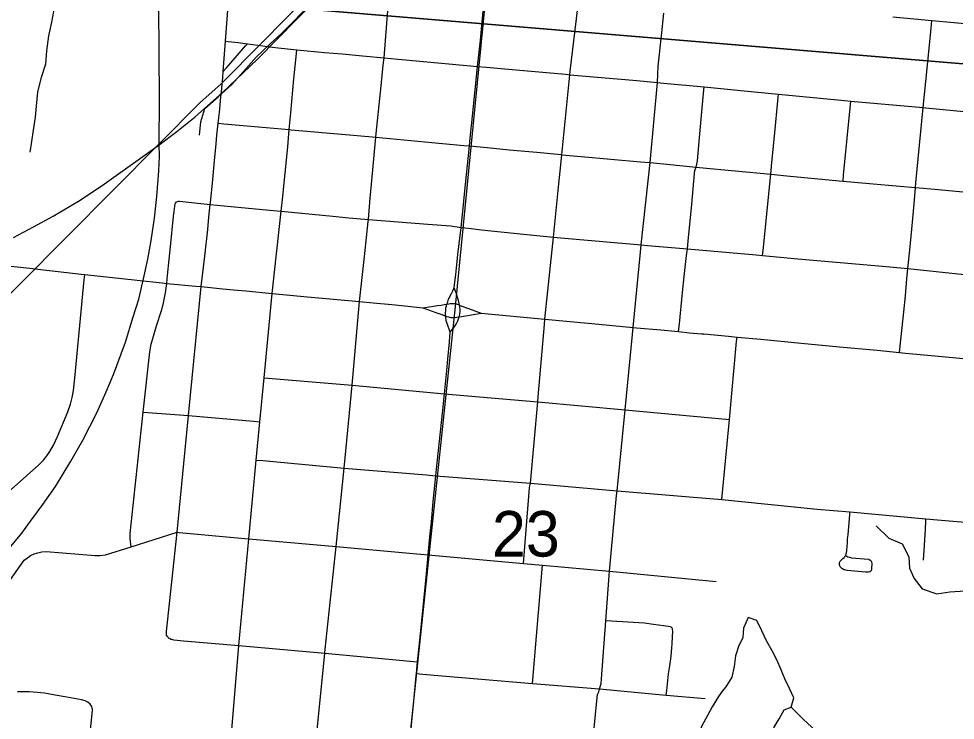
# Model space of a CAD drawing. Extents: x 0 to 1067, y 0 to 440.
# Drawn here: x 801.667 to 802.528, y 351.834 to 352.478 of the extents above; entities that cross this region are included whole.
import ezdxf

# ---------------------------------------------------------------- set-up
doc = ezdxf.new("R2010")
doc.units = 0
for name, color, linetype in [('GM_X_City_Street', 7, 'Continuous'), ('GM_X_Minor_Lake', 7, 'Continuous'), ('GM_X_Minor_River', 7, 'Continuous'), ('GM_X_Rail_Line', 7, 'Continuous'), ('GM_X_Section', 7, 'Continuous'), ('GM_X_Section_Text', 7, 'Continuous'), ('GM_X_State_Route', 7, 'Continuous'), ('GM_X_US_Route', 7, 'Continuous')]:
    doc.layers.add(name, color=color, linetype=linetype)

msp = doc.modelspace()

# ---------------------------------------------------------------- linework, layer by layer
at = {"layer": 'GM_X_City_Street'}
for p, q in [((801.90043, 352.22587), (801.90867, 352.30157)), ((801.89306, 352.14836), (801.90043, 352.22587)), ((801.89306, 352.14836), (801.9737, 352.14146)), ((801.9737, 352.14146), (802.05865, 352.1337)), ((802.05865, 352.1337), (802.14441, 352.12612)), ((802.14441, 352.12612), (802.22463, 352.11878)), ((802.22463, 352.11878), (802.32063, 352.10989)), ((802.05076, 352.05842), (802.13765, 352.05156)), ((802.13765, 352.05156), (802.21744, 352.04445)), ((802.21744, 352.04445), (802.31357, 352.03647)), ((802.43117, 352.02507), (802.501, 352.01891)), ((801.77068, 351.993), (801.81286, 352.00644)), ((801.87888, 352.00035), (801.95916, 351.99336)), ((802.1395, 351.8674), (802.14869, 351.97616))]:
    msp.add_line(p, q, dxfattribs=at)
for points in [[(802.17382, 352.42684), (802.1742, 352.43015), (802.18315, 352.50645), (802.18406, 352.5112), (802.18522, 352.51941), (802.1918, 352.58708), (802.19873, 352.6575), (802.20495, 352.72824), (802.20556, 352.73524)], [(802.00311, 352.44223), (802.00451, 352.45834), (802.00696, 352.48961), (802.00897, 352.51285)], [(801.83503, 352.23223), (801.8385, 352.26019), (801.84106, 352.28473), (801.84222, 352.29577), (801.84343, 352.30764), (801.84361, 352.30935), (801.84542, 352.32729), (801.84732, 352.34771), (801.84882, 352.36315), (801.8496, 352.37119), (801.85078, 352.38219), (801.85187, 352.39218), (801.85325, 352.4064), (801.85368, 352.41101), (801.85494, 352.42436), (801.85536, 352.42984), (801.85751, 352.45776), (801.85999, 352.49)], [(802.23932, 352.27038), (802.24764, 352.34603), (802.25435, 352.41974), (802.25471, 352.42722), (802.25507, 352.43471), (802.25825, 352.46537), (802.26019, 352.48345)], [(802.47071, 352.47984), (802.49032, 352.47813), (802.50649, 352.47663)], [(802.47665, 352.17162), (802.47728, 352.17745), (802.48064, 352.2089), (802.48218, 352.22371), (802.48352, 352.23916), (802.48441, 352.24872), (802.48621, 352.2657), (802.48807, 352.28484), (802.48904, 352.29466), (802.49005, 352.3082), (802.49144, 352.32326), (802.49181, 352.32737), (802.49853, 352.39661), (802.50104, 352.42052), (802.50578, 352.46932), (802.50649, 352.47663)], [(802.50649, 352.47663), (802.52697, 352.47474), (802.57406, 352.47004), (802.6483, 352.46263), (802.69617, 352.45813), (802.70031, 352.45774)], [(801.85536, 352.42984), (801.85822, 352.4331), (801.86623, 352.4422), (801.87593, 352.45325), (801.87768, 352.45524)], [(801.85751, 352.45776), (801.85999, 352.45747), (801.8691, 352.45641), (801.87768, 352.45524), (801.8824, 352.45463), (801.89157, 352.45337), (801.89535, 352.45286), (801.90581, 352.4516), (801.92292, 352.4497), (801.94829, 352.44728), (801.96495, 352.44588), (801.98338, 352.44412), (802.00311, 352.44223), (802.01593, 352.441), (802.07922, 352.43532), (802.08908, 352.43434)], [(801.90867, 352.30157), (801.90971, 352.31203), (801.91469, 352.36065), (801.916, 352.37632), (801.9173, 352.39191), (801.92027, 352.42315), (801.92257, 352.44614), (801.92292, 352.4497)], [(801.98061, 352.21846), (801.98556, 352.26268), (801.98857, 352.29186), (801.98877, 352.29393), (801.98954, 352.30169), (801.99046, 352.3134), (801.99156, 352.32638), (801.99564, 352.36936), (801.99596, 352.37264), (802.00035, 352.41645), (802.00237, 352.43565), (802.00311, 352.44223)], [(802.08908, 352.43434), (802.09722, 352.4336), (802.11755, 352.43179), (802.1698, 352.42718), (802.17382, 352.42684), (802.2353, 352.42145), (802.25435, 352.41974), (802.25995, 352.41905), (802.29708, 352.41559), (802.33092, 352.41244), (802.36552, 352.40905), (802.42622, 352.40311), (802.43205, 352.40258), (802.49853, 352.39661), (802.50094, 352.3964), (802.66594, 352.38059), (802.69396, 352.37809), (802.73883, 352.37338), (802.75724, 352.37145), (802.81158, 352.36564), (802.86823, 352.36027), (802.87525, 352.35961)], [(802.15083, 352.20225), (802.15869, 352.27757), (802.1638, 352.32651), (802.16488, 352.33818), (802.16641, 352.35331), (802.17382, 352.42684)], [(802.27376, 352.19076), (802.27448, 352.19797), (802.27735, 352.22675), (802.27885, 352.24148), (802.27939, 352.24694), (802.28103, 352.26071), (802.28183, 352.26671), (802.28267, 352.27394), (802.28594, 352.30777), (802.2882, 352.336), (802.2888, 352.33886), (802.28976, 352.342), (802.29058, 352.34459), (802.29099, 352.34759), (802.29336, 352.37248), (802.29685, 352.41292), (802.29708, 352.41559)], [(802.35089, 352.26074), (802.35135, 352.26531), (802.35835, 352.33534), (802.35936, 352.34626), (802.36181, 352.37038), (802.36522, 352.40589), (802.36552, 352.40905)], [(802.42481, 352.32905), (802.42536, 352.33464), (802.43205, 352.40258)], [(801.85078, 352.38219), (801.85599, 352.38175), (801.89481, 352.37844), (801.916, 352.37632), (801.91766, 352.37616), (801.97832, 352.37097), (801.99564, 352.36936), (802.04691, 352.36459), (802.07646, 352.3619), (802.08159, 352.36142)], [(802.08159, 352.36142), (802.09775, 352.3598), (802.1181, 352.35775), (802.14333, 352.3555), (802.16555, 352.35339), (802.16641, 352.35331), (802.18409, 352.35173), (802.23887, 352.34686), (802.24764, 352.34603), (802.2629, 352.34457), (802.28976, 352.342), (802.29299, 352.34156), (802.35835, 352.33534), (802.37325, 352.33392), (802.42128, 352.32937), (802.42481, 352.32905), (802.44912, 352.32686), (802.47707, 352.32447), (802.49144, 352.32326), (802.5125, 352.32139), (802.57344, 352.31554)], [(801.80347, 352.23506), (801.8042, 352.24238), (801.80565, 352.2571), (801.80683, 352.26857), (801.80973, 352.29679), (801.81022, 352.301), (801.81088, 352.30603), (801.81125, 352.30804), (801.81156, 352.30887), (801.812, 352.30956), (801.81255, 352.31005)], [(801.81255, 352.31005), (801.81335, 352.31042), (801.81428, 352.31054), (801.81521, 352.31048), (801.8234, 352.30962), (801.84343, 352.30764)], [(801.84343, 352.30764), (801.84974, 352.30702), (801.89779, 352.30247), (801.90867, 352.30157)], [(801.90867, 352.30157), (801.95603, 352.29688), (801.97088, 352.29543), (801.98877, 352.29393)], [(801.98877, 352.29393), (802.04321, 352.28962), (802.06444, 352.28783), (802.07384, 352.28652)], [(802.07384, 352.28652), (802.08069, 352.28578), (802.09254, 352.28426), (802.13131, 352.28031), (802.15869, 352.27757)], [(802.15869, 352.27757), (802.16565, 352.27687), (802.23932, 352.27038)], [(802.23196, 352.19455), (802.23881, 352.26381), (802.23932, 352.27038)], [(802.23932, 352.27038), (802.24519, 352.26986), (802.28183, 352.26671)], [(802.28183, 352.26671), (802.34489, 352.26129), (802.35089, 352.26074)], [(802.35089, 352.26074), (802.38335, 352.25779), (802.46106, 352.25083), (802.48441, 352.24872)], [(802.48441, 352.24872), (802.56244, 352.24051), (802.64743, 352.23271), (802.68021, 352.22964)], [(801.54142, 351.93653), (801.64877, 352.03567), (801.68589, 352.0683), (801.69012, 352.07275), (801.6932, 352.07655), (801.69594, 352.0806), (801.69928, 352.08649), (801.70309, 352.09426), (801.71259, 352.11716), (801.7149, 352.12418), (801.71639, 352.13016), (801.71766, 352.13681), (801.71909, 352.14787), (801.72769, 352.23821), (801.72818, 352.24333)], [(801.77068, 351.993), (801.77007, 351.99783), (801.76972, 352.0007), (801.76972, 352.00284), (801.76996, 352.0053), (801.78186, 352.11683), (801.78788, 352.17233), (801.78903, 352.17924), (801.79117, 352.18648), (801.79397, 352.19618), (801.79862, 352.21028), (801.80003, 352.21568), (801.80228, 352.22637), (801.80347, 352.23506)], [(801.80377, 351.91096), (801.80331, 351.91182), (801.80323, 351.9133), (801.80331, 351.91519), (801.81286, 352.00644), (801.82338, 352.11383), (801.83503, 352.23223)], [(801.94861, 351.89523), (801.94902, 351.89903), (801.95916, 351.99336), (801.96647, 352.06535), (801.9737, 352.14146), (801.98061, 352.21846)], [(802.14441, 352.12612), (802.14482, 352.131), (802.1504, 352.19728), (802.15083, 352.20225)], [(802.22463, 352.11878), (802.23134, 352.18812), (802.23196, 352.19455)], [(802.31357, 352.03647), (802.32063, 352.10989), (802.32706, 352.18164), (802.32743, 352.18582)], [(801.80213, 351.16675), (801.8013, 351.17215), (801.80017, 351.17959), (801.7997, 351.18585), (801.79963, 351.19398), (801.80009, 351.20458), (801.80122, 351.21948), (801.80786, 351.28468), (801.8177, 351.38392), (801.82687, 351.47329), (801.84121, 351.60878), (801.84709, 351.6664), (801.84758, 351.67119), (801.85164, 351.71085), (801.86171, 351.80665), (801.86972, 351.90238), (801.87888, 352.00035), (801.88565, 352.0728), (801.88897, 352.10787), (801.89306, 352.14836)], [(802.13108, 351.97781), (802.13676, 352.04711), (802.137, 352.049), (802.13765, 352.05156), (802.14441, 352.12612)], [(802.1577, 351.43738), (802.17002, 351.57035), (802.17082, 351.57612), (802.17207, 351.58277), (802.17443, 351.60445), (802.18687, 351.7326), (802.19887, 351.85469), (802.19936, 351.85732), (802.20035, 351.85979), (802.20118, 351.86255), (802.20249, 351.86761), (802.20298, 351.87175), (802.20694, 351.92517), (802.21029, 351.97063), (802.21682, 352.04028), (802.21744, 352.04445), (802.22463, 352.11878)], [(801.78186, 352.11683), (801.82338, 352.11383), (801.88301, 352.10842), (801.88897, 352.10787)], [(801.88565, 352.0728), (801.89164, 352.07225), (801.96647, 352.06535), (802.04214, 352.05913), (802.05076, 352.05842)], [(802.31357, 352.03647), (802.40104, 352.02772), (802.43117, 352.02507)], [(802.42715, 351.98504), (802.42823, 351.98436), (802.42922, 351.98395), (802.43065, 351.98346), (802.4318, 351.98317), (802.43264, 351.98307), (802.44829, 351.98157), (802.44895, 351.98141), (802.45038, 351.98037), (802.45088, 351.97924), (802.45121, 351.97773), (802.45103, 351.97304), (802.45085, 351.97181), (802.45028, 351.97073), (802.44931, 351.96997), (802.44813, 351.96962), (802.44565, 351.96974), (802.4285, 351.97137), (802.42653, 351.97176), (802.42564, 351.97195), (802.42478, 351.97237), (802.4234, 351.97337), (802.42251, 351.9744), (802.42192, 351.97544), (802.42166, 351.97639), (802.42155, 351.97744), (802.42165, 351.97867), (802.42207, 351.9798), (802.42266, 351.98047), (802.42336, 351.98119), (802.42459, 351.98218), (802.42577, 351.98314), (802.42643, 351.98382), (802.42715, 351.98504), (802.42766, 351.98628), (802.42794, 351.98777), (802.42817, 351.98934), (802.42857, 351.99365), (802.4288, 351.99604), (802.42908, 352.00035), (802.42941, 352.00394), (802.43098, 352.02285), (802.43117, 352.02507)], [(802.49869, 351.9809), (802.50048, 352.00875), (802.50089, 352.0168), (802.501, 352.01891)], [(802.501, 352.01891), (802.57988, 352.01196), (802.78606, 351.99348), (802.78954, 351.9933)], [(801.81286, 352.00644), (801.81499, 352.00624), (801.87532, 352.00068), (801.87888, 352.00035)], [(801.63989, 351.93524), (801.67236, 351.98078), (801.6754, 351.98302), (801.67835, 351.98504), (801.6816, 351.98654), (801.68507, 351.9876), (801.68881, 351.98843), (801.69278, 351.98861), (801.73763, 351.98498), (801.74207, 351.98498), (801.74722, 351.98577), (801.77068, 351.993)], [(801.95916, 351.99336), (802.03644, 351.98625), (802.04368, 351.98558)], [(802.04368, 351.98558), (802.13108, 351.97781), (802.14869, 351.97616), (802.21029, 351.97063), (802.30819, 351.96133)], [(802.26244, 351.85678), (802.2629, 351.86107), (802.26405, 351.87323), (802.26446, 351.87624), (802.26503, 351.87989), (802.26561, 351.88384), (802.26626, 351.88787), (802.267, 351.89247), (802.26733, 351.8965), (802.26758, 351.90003), (802.26782, 351.90414), (802.26836, 351.91591), (802.26824, 351.9171), (802.26799, 351.91786), (802.26771, 351.91846), (802.26689, 351.91919), (802.26615, 351.91948), (802.25985, 351.92054), (802.25081, 351.92182), (802.2423, 351.9228), (802.20694, 351.92517)], [(801.80377, 351.91096), (801.80434, 351.91022), (801.80483, 351.90968), (801.80553, 351.90915), (801.80623, 351.90874), (801.80693, 351.90836), (801.80779, 351.90808), (801.80874, 351.90783), (801.80997, 351.90762), (801.81897, 351.9066), (801.86972, 351.90238), (801.94861, 351.89523), (802.02719, 351.8881), (802.03396, 351.8875)], [(801.89977, 351.37443), (801.90939, 351.4666), (801.92074, 351.58012), (801.92522, 351.62328), (801.93277, 351.70382), (801.93277, 351.70826), (801.94049, 351.79589), (801.94023, 351.80036), (801.93989, 351.80609), (801.94861, 351.89523)], [(802.0329, 351.87667), (802.03833, 351.8762), (802.1395, 351.8674), (802.20118, 351.86255), (802.26244, 351.85678), (802.29816, 351.85363)], [(801.71694, 351.66461), (801.71744, 351.66957), (801.71854, 351.68123), (801.72006, 351.69743), (801.72311, 351.7271), (801.72746, 351.76854), (801.73117, 351.80443), (801.73297, 351.8217), (801.73499, 351.83968), (801.73522, 351.84361), (801.73446, 351.84623), (801.73298, 351.84852), (801.73095, 351.85032), (801.7286, 351.8516), (801.72498, 351.85262), (801.7218, 351.85319), (801.71154, 351.8549), (801.70095, 351.8569), (801.69107, 351.85853), (801.68423, 351.85931), (801.67694, 351.85987), (801.67133, 351.85995), (801.66615, 351.85975)]]:
    msp.add_lwpolyline(points, dxfattribs=at)
at = {"layer": 'GM_X_Minor_Lake'}
for points in [[(802.37713, 351.84584), (802.37947, 351.85416), (802.37576, 351.86291), (802.37129, 351.87167), (802.36796, 351.88003), (802.36387, 351.88917), (802.35978, 351.89754), (802.35456, 351.90668), (802.35009, 351.91582), (802.34563, 351.92533), (802.33771, 351.92805), (802.33347, 351.91822), (802.33264, 351.90989), (802.32879, 351.90157), (802.32607, 351.89287), (802.32485, 351.88303), (802.3225, 351.87319), (802.31713, 351.86451), (802.31392, 351.86029)], [(802.31392, 351.86029), (802.31025, 351.85546), (802.30449, 351.84603), (802.30027, 351.8381), (802.29489, 351.8279), (802.29063, 351.81618), (802.28829, 351.80824), (802.28671, 351.79953), (802.28891, 351.79117), (802.29641, 351.78391), (802.30432, 351.7793), (802.31339, 351.77809), (802.32098, 351.78068), (802.32748, 351.78859), (802.33171, 351.7969), (802.34162, 351.8063), (802.35, 351.81268), (802.35724, 351.81983), (802.36147, 351.82738), (802.36607, 351.83493), (802.37068, 351.84323), (802.37713, 351.84584)]]:
    msp.add_lwpolyline(points, dxfattribs=at)
at = {"layer": 'GM_X_Minor_River'}
for points in [[(801.67802, 352.35571), (801.67934, 352.36556), (801.68103, 352.37578), (801.68277, 352.38791), (801.6837, 352.39777), (801.68506, 352.41066), (801.68835, 352.42465), (801.69236, 352.43673), (801.69333, 352.44887), (801.69508, 352.46251), (801.69796, 352.475), (801.69965, 352.48484), (801.70025, 352.49736), (801.70199, 352.50949), (801.70296, 352.52162), (801.70205, 352.53455), (801.69734, 352.54754), (801.69189, 352.5613)], [(801.83354, 352.3713), (801.83489, 352.38343), (801.83853, 352.3959), (801.85086, 352.40671), (801.86321, 352.41789), (801.87404, 352.42986), (801.88566, 352.44295), (801.89841, 352.45527), (801.90882, 352.46458), (801.92041, 352.47616), (801.93201, 352.48849)], [(802.45531, 352.01243), (802.46694, 352.00097), (802.47901, 351.99594), (802.48534, 351.98376), (802.48601, 351.97352), (802.4901, 351.96401), (802.49758, 351.95447), (802.51116, 351.94981), (802.52291, 351.95161), (802.53692, 351.95264)], [(802.37713, 351.84584), (802.38839, 351.83437), (802.39966, 351.82443)]]:
    msp.add_lwpolyline(points, dxfattribs=at)
at = {"layer": 'GM_X_Rail_Line'}
for points in [[(801.66253, 352.27717), (801.68099, 352.28704), (801.69903, 352.2968), (801.72375, 352.31155), (801.74635, 352.3264), (801.79653, 352.36237), (801.81266, 352.37457), (801.82942, 352.38825), (801.84374, 352.40067), (801.85425, 352.41011), (801.88681, 352.44106), (801.92324, 352.47806), (801.98504, 352.54062), (802.13232, 352.68981), (802.14608, 352.70422), (802.15529, 352.71538), (802.16941, 352.73248)], [(801.7963, 352.3629), (801.83379, 352.40111), (801.85338, 352.41832), (801.89076, 352.45611), (801.95513, 352.52157), (802.02993, 352.59544), (802.06825, 352.63787), (802.11388, 352.6823), (802.13313, 352.70104)], [(801.75489, 350.8021), (801.97049, 351.25596), (802.0144, 351.70062), (802.0688, 352.21399), (802.10298, 352.56286), (802.12058, 352.63402), (802.13109, 352.68934)], [(801.65711, 351.98968), (801.6703, 352.00571), (801.67814, 352.01653), (801.68963, 352.03206), (801.70112, 352.04854), (801.71526, 352.07162), (801.72643, 352.09119), (801.73919, 352.11618), (801.74781, 352.13554), (801.75451, 352.15128), (801.76567, 352.18117), (801.77259, 352.20446), (801.7778, 352.22073), (801.78195, 352.23924), (801.78609, 352.25742), (801.78918, 352.27444), (801.79205, 352.29507), (801.79428, 352.31496), (801.79609, 352.33836), (801.79684, 352.35187), (801.79653, 352.36237), (801.79686, 352.40441), (801.79582, 352.53276)], [(801.7963, 352.3629), (801.54164, 352.10688), (801.36391, 351.92721)]]:
    msp.add_lwpolyline(points, dxfattribs=at)
at = {"layer": 'GM_X_Section'}
for points in [[(801.74318, 353.49934), (802.78288, 353.41246), (802.69313, 352.42359), (801.6612, 352.51006)], [(802.69313, 352.42359), (802.59985, 351.39962), (801.55946, 351.49882), (801.6612, 352.51006)]]:
    msp.add_lwpolyline(points, close=True, dxfattribs=at)
at = {"layer": 'GM_X_State_Route'}
for p, q in [((801.80347, 352.23506), (801.8301, 352.23268)), ((801.8301, 352.23268), (801.83503, 352.23223)), ((802.09221, 352.20761), (802.15083, 352.20225)), ((802.23196, 352.19455), (802.235, 352.19429))]:
    msp.add_line(p, q, dxfattribs=at)
for points in [[(801.62748, 352.25425), (801.64004, 352.25293), (801.68049, 352.24868)], [(801.68049, 352.24868), (801.68494, 352.24821), (801.72752, 352.24339), (801.72818, 352.24333)], [(801.72818, 352.24333), (801.77629, 352.23799), (801.79916, 352.23548), (801.80347, 352.23506)], [(801.83503, 352.23223), (801.85482, 352.23012), (801.86466, 352.22919), (801.87604, 352.22811), (801.90043, 352.22587)], [(801.90043, 352.22587), (801.93283, 352.22262), (801.9567, 352.22051), (801.98061, 352.21846)], [(801.98061, 352.21846), (801.99297, 352.2173), (802.0102, 352.21558), (802.02492, 352.21404), (802.03861, 352.21261)], [(802.03861, 352.21261), (802.04398, 352.21064), (802.05076, 352.20829), (802.05518, 352.2067), (802.05759, 352.2059), (802.05958, 352.20525)], [(802.05958, 352.20525), (802.06081, 352.20476), (802.06232, 352.2043), (802.06335, 352.20406), (802.06436, 352.20387), (802.06551, 352.20375)], [(802.06551, 352.20375), (802.067, 352.20372), (802.06851, 352.20381), (802.0701, 352.20401), (802.0722, 352.20435)], [(802.0722, 352.20435), (802.07817, 352.20518), (802.09221, 352.20761)], [(802.15083, 352.20225), (802.17396, 352.20013), (802.20039, 352.19771), (802.23196, 352.19455)], [(802.235, 352.19429), (802.25728, 352.19236), (802.27376, 352.19076)], [(802.27376, 352.19076), (802.28385, 352.18978), (802.29483, 352.18879)], [(802.29483, 352.18879), (802.29683, 352.18861), (802.31968, 352.18655), (802.32743, 352.18582)], [(802.32743, 352.18582), (802.34937, 352.18377), (802.38645, 352.18015), (802.42169, 352.17691), (802.45632, 352.1736), (802.47665, 352.17162)], [(802.47665, 352.17162), (802.48225, 352.17107), (802.51254, 352.16817), (802.54828, 352.16475), (802.58048, 352.16167), (802.62648, 352.15726), (802.65718, 352.15425), (802.6737, 352.15272)]]:
    msp.add_lwpolyline(points, dxfattribs=at)
at = {"layer": 'GM_X_US_Route'}
for p, q in [((801.80347, 352.23506), (801.8301, 352.23268)), ((801.8301, 352.23268), (801.83503, 352.23223)), ((802.09221, 352.20761), (802.15083, 352.20225)), ((802.23196, 352.19455), (802.235, 352.19429))]:
    msp.add_line(p, q, dxfattribs=at)
for points in [[(802.06758, 352.23098), (802.06928, 352.2461), (802.071, 352.26151), (802.07384, 352.28652), (802.07579, 352.30423), (802.07707, 352.31718), (802.08159, 352.36142), (802.08231, 352.36845), (802.08433, 352.38885), (802.08876, 352.43084), (802.08908, 352.43434), (802.09162, 352.45865), (802.09484, 352.49199), (802.09506, 352.49445), (802.09525, 352.4963), (802.09573, 352.50121)], [(801.62748, 352.25425), (801.64004, 352.25293), (801.68049, 352.24868)], [(801.68049, 352.24868), (801.68494, 352.24821), (801.72752, 352.24339), (801.72818, 352.24333)], [(801.72818, 352.24333), (801.77629, 352.23799), (801.79916, 352.23548), (801.80347, 352.23506)], [(801.83503, 352.23223), (801.85482, 352.23012), (801.86466, 352.22919), (801.87604, 352.22811), (801.90043, 352.22587)], [(802.06396, 352.19016), (802.06104, 352.19835), (802.06027, 352.20083), (802.06002, 352.20194), (802.0598, 352.20313), (802.05958, 352.20525), (802.05953, 352.20724), (802.05975, 352.21077), (802.05996, 352.21269), (802.06034, 352.21431), (802.06091, 352.21594), (802.06127, 352.21719), (802.06157, 352.21814), (802.06202, 352.21941), (802.06244, 352.2205), (802.06292, 352.22165), (802.06394, 352.22377), (802.06493, 352.22587), (802.06618, 352.22825), (802.06758, 352.23098)], [(802.0722, 352.20435), (802.07247, 352.20573), (802.07262, 352.20681), (802.07289, 352.20956), (802.07289, 352.21163), (802.07281, 352.21284), (802.07262, 352.21392), (802.0724, 352.21501), (802.07206, 352.21674), (802.07151, 352.21928), (802.07069, 352.22224), (802.06973, 352.22542), (802.06884, 352.22794), (802.06758, 352.23098)], [(801.90043, 352.22587), (801.93283, 352.22262), (801.9567, 352.22051), (801.98061, 352.21846)], [(801.98061, 352.21846), (801.99297, 352.2173), (802.0102, 352.21558), (802.02492, 352.21404), (802.03861, 352.21261)], [(802.03861, 352.21261), (802.04455, 352.2135), (802.04842, 352.21408), (802.05227, 352.2147), (802.05569, 352.21521), (802.0583, 352.21558), (802.06091, 352.21594), (802.06259, 352.2163), (802.06376, 352.2165), (802.06487, 352.21663), (802.06661, 352.21664), (802.06785, 352.2165), (802.06948, 352.21618), (802.07115, 352.21556), (802.0724, 352.21501), (802.07442, 352.21428), (802.07979, 352.21232), (802.08417, 352.21069), (802.09221, 352.20761)], [(802.03861, 352.21261), (802.04398, 352.21064), (802.05076, 352.20829), (802.05518, 352.2067), (802.05759, 352.2059), (802.05958, 352.20525)], [(802.05958, 352.20525), (802.06081, 352.20476), (802.06232, 352.2043), (802.06335, 352.20406), (802.06436, 352.20387), (802.06551, 352.20375)], [(802.06396, 352.19016), (802.06762, 352.19487), (802.06948, 352.19763), (802.07094, 352.20071), (802.0722, 352.20435)], [(802.06551, 352.20375), (802.067, 352.20372), (802.06851, 352.20381), (802.0701, 352.20401), (802.0722, 352.20435)], [(802.0722, 352.20435), (802.07817, 352.20518), (802.09221, 352.20761)], [(802.15083, 352.20225), (802.17396, 352.20013), (802.20039, 352.19771), (802.23196, 352.19455)], [(802.05076, 352.05842), (802.05136, 352.06438), (802.05385, 352.08736), (802.05709, 352.11872), (802.05865, 352.1337), (802.06081, 352.15514), (802.0618, 352.1654), (802.06332, 352.18136), (802.06396, 352.19016)], [(802.235, 352.19429), (802.25728, 352.19236), (802.27376, 352.19076)], [(802.27376, 352.19076), (802.28385, 352.18978), (802.29483, 352.18879)], [(802.29483, 352.18879), (802.29683, 352.18861), (802.31968, 352.18655), (802.32743, 352.18582)], [(802.32743, 352.18582), (802.34937, 352.18377), (802.38645, 352.18015), (802.42169, 352.17691), (802.45632, 352.1736), (802.47665, 352.17162)], [(802.47665, 352.17162), (802.48225, 352.17107), (802.51254, 352.16817), (802.54828, 352.16475), (802.58048, 352.16167), (802.62648, 352.15726), (802.65718, 352.15425), (802.6737, 352.15272)], [(802.02761, 351.82228), (802.02883, 351.8358), (802.03006, 351.84779), (802.03268, 351.87453), (802.0329, 351.87667), (802.03396, 351.8875), (802.03476, 351.89579), (802.03651, 351.91299), (802.03802, 351.92853), (802.0392, 351.94037), (802.04202, 351.9681), (802.04368, 351.98558), (802.04555, 352.00514), (802.04655, 352.01568), (802.04838, 352.03479), (802.05076, 352.05842)]]:
    msp.add_lwpolyline(points, dxfattribs=at)

# ---------------------------------------------------------------- texts
at = {"layer": 'GM_X_Section_Text'}
msp.add_text('23', height=0.041856, rotation=0.00001, dxfattribs=at).set_placement((802.10228, 351.98408))

doc.saveas('drawing.dxf')
